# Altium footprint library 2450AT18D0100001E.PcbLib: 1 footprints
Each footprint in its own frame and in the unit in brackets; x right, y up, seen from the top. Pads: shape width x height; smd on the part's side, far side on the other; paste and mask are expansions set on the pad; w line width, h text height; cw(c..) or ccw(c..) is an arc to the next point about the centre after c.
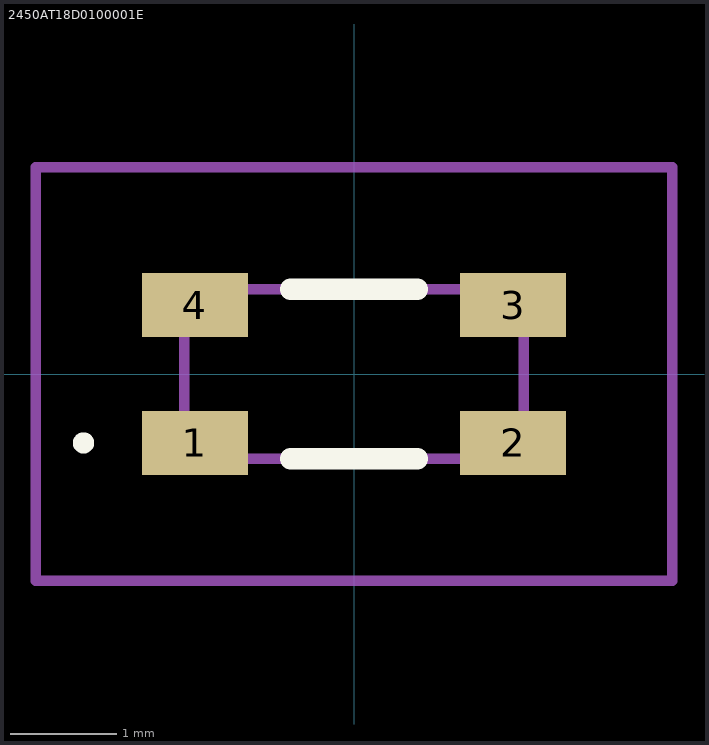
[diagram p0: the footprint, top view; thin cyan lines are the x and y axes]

## 2450AT18D0100001E [mm]
pads (4):
  rect 1x0.6 smd: 1(-1.5,-0.65) 2(1.5,-0.65) 3(1.5,0.65) 4(-1.5,0.65)
Top Overlay:
  lines w0.1: -2.6,-0.65 cw(c-2.55,-0.65) -2.5,-0.65 ; -2.6,-0.65 -2.6,-0.65 ; -2.6,-0.65 ccw(c-2.55,-0.65) -2.5,-0.65 ; -2.5,-0.65 -2.5,-0.65
  lines w0.2: -0.6,-0.8 0.6,-0.8 ; -0.6,0.8 0.6,0.8
Mechanical 15:
  lines w0.1: -1.6,-0.8 1.6,-0.8 1.6,0.8 -1.6,0.8 -1.6,-0.8
Mechanical 20:
  lines w0.1: -3,-1.95 3,-1.95 3,1.95 -3,1.95 -3,-1.95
